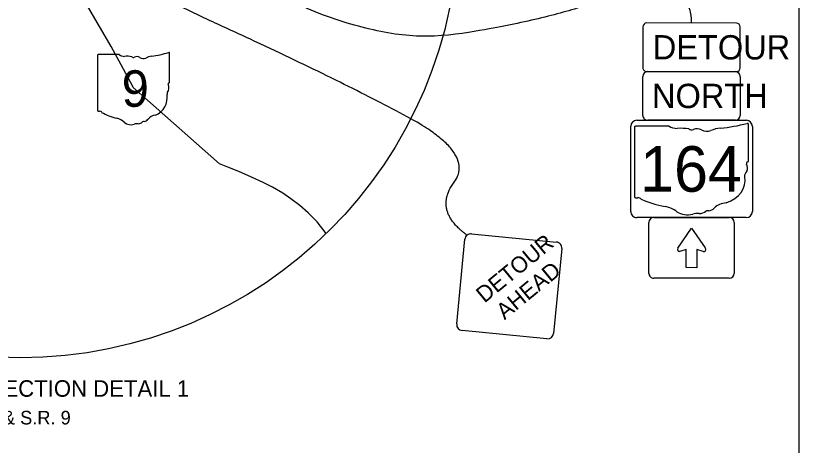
# Model space of a CAD drawing. Extents: x -202 to 1556, y 0 to 676.
# Drawn here: x 189 to 350, y 220.2 to 308.6 of the extents above; entities that cross this region are included whole.
import ezdxf

# ---------------------------------------------------------------- set-up
doc = ezdxf.new("R2010")
doc.units = 0
for name, color, linetype in [('Default', 7, 'Continuous'), ('GM_X_City_Street', 7, 'Continuous'), ('GM_X_Minor_Lake', 7, 'Continuous'), ('GM_X_Minor_River_Text', 7, 'Continuous'), ('SH_Data', 7, 'Continuous')]:
    doc.layers.add(name, color=color, linetype=linetype)

msp = doc.modelspace()

# ---------------------------------------------------------------- linework, layer by layer
at = {"layer": 'Default'}
msp.add_lwpolyline([(252.82, 263.77), (250.94, 266.18), (249.11, 268.01), (247.41, 269.5), (245.58, 270.91), (243.93, 272.06), (241.8, 273.32), (239.87, 274.28), (237.5, 275.33), (234.85, 276.49), (232.64, 277.4), (230.92, 278.07), (213.17, 293.79), (213.07, 293.99), (210.74, 298.43), (208.63, 302.2), (204.04, 310.12), (199.77, 316.15), (195.3, 321.52), (193.27, 323.98), (192.02, 325.52), (191.59, 326.08), (191.21, 326.62), (190, 328.22)], dxfattribs=at)
at = {"layer": 'GM_X_City_Street'}
for p, q in [((205.82, 300.36), (205.82, 289.1)), ((210.31, 300.55), (205.97, 300.55)), ((220.65, 294.94), (220.65, 300.83)), ((220.65, 294.94), (220.65, 294.94))]:
    msp.add_line(p, q, dxfattribs=at)
for centre, radius, start, end in [((215.37, 315.9), 15.73, 275.8445, 288.9065), ((220.49, 300.85), 0.165, 351.8621, 97.738), ((205.99, 300.38), 0.172, 98.1301, 188.1301), ((211.34, 301.86), 1.67, 231.6195, 271.1119), ((211.9, 294.23), 5.98, 80.4867, 94.9883), ((213.26, 300.44), 0.481, 219.7921, 297.1024), ((213.96, 299.14), 1, 54.4667, 119.1411), ((215.25, 300.92), 1.2, 233.8562, 294.8282), ((217.37, 297.11), 3.16, 97.3462, 120.7689), ((220.61, 294.51), 0.256, 107.944, 210.337), ((220.48, 294.92), 0.177, 289.6038, 7.7341), ((221.24, 292.48), 1.12, 136.8065, 186.9296), ((218.99, 293.76), 1.53, 340.033, 23.6496), ((216.25, 291.73), 3.93, 292.3089, 8.9858), ((205.99, 289.08), 0.173, 171.9584, 258.3066), ((206.02, 290.23), 1.32, 267.339, 280.6039), ((206.29, 288.45), 0.477, 29.7484, 93.2717), ((212.31, 298.56), 11.36, 240.4129, 257.1985), ((208.92, 284.04), 3.55, 47.1842, 75.836), ((212.77, 288.39), 2.26, 230.7004, 286.2918), ((214.24, 287.55), 1.2, 268.777, 315.5493), ((215.32, 286.46), 0.338, 65.7517, 132.6484), ((215.18, 288.01), 1.27, 282.8732, 323.2771), ((217.91, 285.94), 2.15, 94.4031, 142.5768), ((214.07, 284.5), 1.85, 85.6951, 111.2099)]:
    msp.add_arc(centre, radius, start, end, dxfattribs=at)
at = {"layer": 'GM_X_Minor_Lake'}
for p, q in [((318.87, 297.06), (336.87, 297.05)), ((317.87, 288.06), (317.87, 296.06)), ((337.87, 296.05), (337.87, 288.05)), ((336.87, 287.05), (318.87, 287.06)), ((316.15, 285.59), (316.14, 271.36)), ((323.24, 285.83), (316.38, 285.83)), ((339.58, 278.74), (339.59, 286.18)), ((339.58, 278.74), (339.58, 278.74)), ((319.11, 255.56), (319.11, 266.06)), ((320.11, 267.06), (335.61, 267.06)), ((336.61, 266.06), (336.61, 255.56)), ((325.02, 260.73), (327.86, 264.87)), ((327.86, 264.87), (330.65, 260.79)), ((326.76, 260.5), (325.48, 260.1)), ((326.76, 256.75), (326.76, 260.5)), ((330.24, 260.1), (328.95, 260.49)), ((328.95, 260.49), (328.95, 256.74)), ((328.95, 256.74), (326.76, 256.75)), ((335.61, 254.56), (320.11, 254.56))]:
    msp.add_line(p, q, dxfattribs=at)
for points in [[(317.87, 306.26), (317.87, 297.86)], [(337.07, 307.05), (318.67, 307.06)], [(337.87, 297.85), (337.87, 306.25)], [(318.67, 297.06), (337.07, 297.05)], [(316.62, 287.06), (339.12, 287.05)], [(315.36, 268.31), (315.37, 285.81)], [(340.37, 285.8), (340.36, 268.3)], [(339.11, 267.05), (316.61, 267.06)], [(279.63, 245.17), (281.31, 262.59)], [(282.68, 263.71), (300.1, 262.02)], [(301.22, 260.66), (299.53, 243.24)], [(298.17, 242.12), (280.75, 243.8)]]:
    msp.add_lwpolyline(points, dxfattribs=at)
for centre, radius, start, end in [((318.67, 306.26), 0.8, 89.9827, 179.9827), ((337.07, 306.25), 0.8, 359.9827, 89.9827), ((318.67, 297.86), 0.8, 179.9827, 269.9827), ((337.07, 297.85), 0.8, 269.9827, 359.9827), ((318.87, 296.06), 1, 89.9827, 179.9827), ((336.87, 296.05), 1, 359.9827, 89.9827), ((316.62, 285.81), 1.25, 89.9827, 179.9827), ((318.87, 288.06), 1, 179.9827, 269.9827), ((336.87, 288.05), 1, 269.9827, 359.9827), ((339.12, 285.8), 1.25, 359.9827, 89.9827), ((316.61, 268.31), 1.25, 179.9827, 269.9827), ((339.11, 268.3), 1.25, 269.9827, 359.9827), ((320.11, 266.06), 1, 89.9827, 179.9827), ((335.61, 266.06), 1, 359.9827, 89.9827), ((282.56, 262.47), 1.25, 84.4693, 174.4693), ((299.98, 260.78), 1.25, 354.4693, 84.4693), ((330.36, 260.49), 0.417, 252.7781, 44.9923), ((325.36, 260.5), 0.417, 145.3939, 287.1873), ((320.11, 255.56), 1, 179.9827, 269.9827), ((335.61, 255.56), 1, 269.9827, 359.9827), ((280.87, 245.05), 1.25, 174.4693, 264.4693), ((298.29, 243.36), 1.25, 264.4693, 354.4693)]:
    msp.add_arc(centre, radius, start, end, dxfattribs=at)
for centre, major_axis, start_param, end_param in [((316.42, 285.62), (0.272, 0), 1.712693, 3.28349), ((324.88, 287.48), (2.63, 0), 4.042523, 4.731795), ((325.75, 277.84), (9.45, 0), 1.404758, 1.657858), ((327.9, 285.69), (0.76, 0), 3.836095, 5.185415), ((329.01, 284.04), (1.58, 0), 0.950623, 2.079405), ((331.05, 286.3), (1.9, 0), 4.081561, 5.145723), ((334.41, 281.48), (5, 0), 1.699011, 2.107814), ((331.24, 305.23), (24.85, -0.01), 4.814394, 5.042369), ((339.33, 286.21), (0.261, 0), 6.141152, 7.989035), ((339.52, 278.19), (0.404, 0), 1.883978, 3.671073), ((339.3, 278.71), (0.279, 0), 5.05454, 6.418171), ((336.95, 277.25), (2.42, 0), 5.934695, 6.695948), ((332.63, 274.67), (6.22, 0), 5.101752, 6.440018), ((340.52, 275.62), (1.76, 0), 2.387724, 3.262537), ((316.41, 271.33), (0.274, 0), 3.00124, 4.508301), ((316.46, 272.78), (2.09, 0), 4.665946, 4.897461), ((316.88, 270.54), (0.754, 0), 0.519207, 1.627899), ((326.4, 283.32), (17.95, -0.01), 4.195997, 4.488961), ((321.05, 264.96), (5.62, 0), 0.823519, 1.323587), ((330.93, 269.97), (2.01, 0), 4.937069, 5.64225), ((335.24, 267.36), (3.4, 0), 1.647645, 2.488434), ((327.12, 270.46), (3.56, 0), 4.026481, 4.996735), ((329.18, 265.54), (2.93, 0), 1.495662, 1.94098), ((329.44, 269.4), (1.9, 0), 4.691044, 5.507374), ((331.16, 268.02), (0.535, 0), 1.147584, 2.315152)]:
    msp.add_ellipse(centre, major_axis=major_axis, ratio=0.8, start_param=start_param, end_param=end_param, dxfattribs=at)
at = {"layer": 'GM_X_Minor_River_Text'}
msp.add_line((350, 10), (350, 430), dxfattribs=at)
at = {"layer": 'SH_Data'}
msp.add_circle((190, 328.22), 90, dxfattribs=at)
for points in [[(327.87, 307.06), (327.87, 312.46), (319.07, 315.68), (299.39, 307.93), (261.96, 301.8), (211.63, 330.38), (195.44, 326.28), (192.62, 329.63)], [(115.11, 240.28), (125.43, 240.28), (140.66, 244.18), (172.28, 309.41), (189.07, 325.53)], [(281.76, 263.43), (274.75, 268.5), (283.53, 280.28), (254.72, 295.67), (211.15, 315.72), (198.85, 323.43)]]:
    msp.add_open_spline(points, degree=2, dxfattribs=at)

# ---------------------------------------------------------------- texts
at = {"layer": 'GM_X_City_Street'}
msp.add_text('9', height=7.5, dxfattribs=at).set_placement((210.82, 289.83))
at = {"layer": 'GM_X_Minor_Lake'}
for s, height, rotation, p in [('DETOUR', 5, 359.9827, (319.9, 299.56)), ('NORTH', 5, 359.9827, (319.74, 289.56)), ('164', 9.375, 359.9827, (317.29, 272.36)), ('DETOUR', 3.333, 39.4693, (285.33, 249.35)), ('AHEAD', 3.333, 39.4693, (289.46, 245.91))]:
    msp.add_text(s, height=height, rotation=rotation, dxfattribs=at).set_placement(p)
at = {"layer": 'GM_X_Minor_River_Text'}
for s, height, p in [('DETOUR INTERSECTION DETAIL 1', 3.4, (149.39, 230.2)), ('S.R. 164 & S.R. 9', 2.8, (170.8, 224.5))]:
    msp.add_text(s, height=height, dxfattribs=at).set_placement(p)

doc.saveas('drawing.dxf')
